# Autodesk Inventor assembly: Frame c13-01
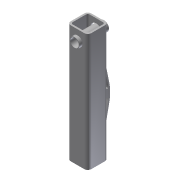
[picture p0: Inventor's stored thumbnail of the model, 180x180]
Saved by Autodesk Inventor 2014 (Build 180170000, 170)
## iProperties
Created: 2011-01
Part Number: Frame c13-01
Document SubType Name: Assembly
Designer: Thom Tremblay
_FrameDoc: Frame Assembly
_Version: 15.0.0
Author: Thom Tremblay
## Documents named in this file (10)
- C:\Inventor 2014 Essentials\Assemblies\Chapter 13\Frame\Frame c13-01.iam
- C:\Inventor 2014 Essentials\Assemblies\Chapter 13\Frame\Skeleton c13-01.ipt
- C:\Inventor 2014 Essentials\Assemblies\Chapter 13\Frame\ISO 70x70x6 00000001.ipt
- ISO 70x70x6 00000001.ipt
- C:\Inventor 2014 Essentials\Assemblies\Chapter 13\Frame\ISO 30x 5 00000002.ipt
- ISO 30x 5 00000002.ipt
- C:\Inventor 2014 Essentials\Assemblies\Chapter 13\Frame\ISO 28x 28_ 00000003.ipt
- ISO 28x 28_ 00000003.ipt
- C:\Inventor 2014 Essentials\Assemblies\Chapter 13\Frame\ISO 33.7x2.5 00000005.ipt
- ISO 42.4x3.0 00000004.ipt
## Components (5 placed, 5 different names)
1. Frame Reference Model
2. ISO 70x70x6 00000001:1
3. ISO 30x 5 00000002:1
4. ISO 28x 28_ 00000003:1
5. ISO 33.7x2.5 00000005:1
